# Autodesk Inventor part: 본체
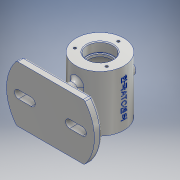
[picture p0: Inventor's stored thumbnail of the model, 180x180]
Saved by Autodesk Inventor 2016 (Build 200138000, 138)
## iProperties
Created: 2017-12
Part Number: 본체
Material: 알루미늄 6061
Document SubType Name: Modeling
Designer: 605-03
Density: 2.7 g/cm^3
Appearance: 알루미늄 - 평지
Mass: 464.488 g
Surface Area: 487.59 cm^2
Volume: 172.033 cm^3
Author: 605-03
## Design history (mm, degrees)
sketch "스케치1"
  geometry: L1 (0, 0)-(30, 0); L2 (30, 0)-(30, -70); L3 (30, -70)-(0, -70); L4 (0, 0)-(0, -70); L5 (16, 0)-(16, -11.7); L6 (15.7, -12)-(14, -12); L7 (14, -12)-(14, -15); L8 (14, -15)-(22, -15); L9 (25, -18)-(25, -52); L10 (22, -55)-(14, -55); L11 (14, -55)-(14, -58); L12 (14, -58)-(15.7, -58); L13 (16, -58.3)-(16, -70); A1 r 0.3 centre (15.7, -58.3) between (16, -58.3) and (15.7, -58); A2 r 0.3 centre (15.7, -11.7) between (15.7, -12) and (16, -11.7); A3 r 3 centre (22, -18) between (25, -18) and (22, -15); A4 r 3 centre (22, -52) between (22, -55) and (25, -52); 4 further points
  constraints: 26 end point, 10 perpendicular, 10 point on line, 8 point on circle, 8 tangent, 4 centre point, 2 vertical, 1 equal radius, 1 horizontal
  dimensions: "d0" = 60 diameter of L2 L4; "d1" = 70 distance of L1.start L3.end; "d2" = 12 distance of L5.start point (16, -12); "d3" = 12 distance of point (16, -58) L13.end; "d4" = 40 distance of point (25, -15) point (25, -55); "d5" = 3 distance of L10.end L11.end; "d6" = 32 diameter of L5 L4; "d7" = 28 diameter of L7 L4; "d8" = 50 diameter of L9 L4; "d9" = 32 diameter of L13 L4; "d10" = 28 diameter of L11 L4; "d11" = 0.3 radius of A1; "d12" = 3 radius of A3; "d13" = 3 radius of A4
revolve "회전1" sketch "스케치1" stored, may be unused: angle "d14" = 90 deg
sketch "스케치2" dims "d15" = 46
  geometry: C1 r 30 at (0, 0) reference; C2 r 16 at (0, 0) reference; 5 further points
  constraints: 2 vertical alignment, 1 coincident, 6 other
  dimensions: "d18" = 360 deg dimension on point (0, 0) point (0, 23) (derived)
hole "구멍1" sketch "스케치2" at (0, 23), (-19.919, -11.5), (19.919, -11.5) diameter "d20" = 3.242; stored, may be unused: countersink angle "d24" = 90 deg, drill point angle "d26" = 118 deg; dims "d21" = 8, "d22" = 4, "d23" = 2, "d25" = 10
sketch "스케치3" dims "d27" = 46
  geometry: C1 r 30 at (0, 0) reference; C2 r 16 at (0, 0) reference; 5 further points
  constraints: 2 vertical alignment, 1 coincident, 6 other
  dimensions: "d30" = 360 deg dimension on point (0, 0) point (0, 23) (derived)
hole "구멍2" sketch "스케치3" at (0, 23), (-19.919, -11.5), (19.919, -11.5) diameter "d32" = 3.242; stored, may be unused: countersink angle "d36" = 90 deg, drill point angle "d38" = 118 deg; dims "d33" = 8, "d34" = 4, "d35" = 2, "d37" = 10
node "작업 평면2"
sketch "스케치6"
  geometry: L1 (42.426, -70)-(-42.426, -70); L2 (42.426, 0)-(-42.426, 0); L3 (-30, 0)-(30, 0) reference; L4 (-30, -70)-(30, -70) reference; L5 (0, 0)-(0, -70); L6 (-16, -70)-(16, -70) reference; A1 r 55 centre (0, -35) between (-42.426, 0) and (-42.426, -70); A2 r 55 centre (0, -35) between (42.426, -70) and (42.426, 0); 2 further points
  constraints: 6 end point, 4 point on circle, 3 midpoint, 2 centre point, 2 horizontal, 1 coincident, 1 vertical alignment
  dimensions: "d58" = 70 distance between parallel lines of L1 L2; "d59" = 35 distance from line of L2 A1.centre; "d60" = 110 diameter of A1; "d61" = 55 radius of A2
extrude "돌출2" join sketch "스케치6" distance "d62" = 10; taper "d63" = 0 deg
sketch "스케치7"
  geometry: L1 (42.426, 0)-(-42.426, 0) reference; L2 (-42.426, 70)-(42.426, 70) reference; L3 (42.426, 0)-(-42.426, 0) reference; L4 (-42.426, 0)-(-42.426, 70); L5 (-42.426, 70)-(42.426, 70) reference; L6 (42.426, 70)-(42.426, 0); L7 (0, 20)-(0, 50); L8 (5, 20)-(5, 50); L9 (-5, 50)-(-5, 20); L10 (-42.426, 35)-(42.426, 35); L11 (-40, 35)-(-24, 35); L12 (-40, 30)-(-24, 30); L13 (-24, 40)-(-40, 40); L14 (24, 35)-(40, 35); L15 (24, 30)-(40, 30); L16 (40, 40)-(24, 40); A1 r 55 centre (0, 35) between (42.426, 0) and (42.426, 70) reference; A2 r 55 centre (0, 35) between (-42.426, 70) and (-42.426, 0) reference; A3 r 5 centre (0, 20) between (-5, 20) and (5, 20); A4 r 5 centre (0, 50) between (5, 50) and (-5, 50); A5 r 5 centre (-40, 35) between (-40, 40) and (-40, 30); A6 r 5 centre (-24, 35) between (-24, 30) and (-24, 40); A7 r 5 centre (24, 35) between (24, 40) and (24, 30); A8 r 5 centre (40, 35) between (40, 30) and (40, 40); 5 further points
  constraints: 30 end point, 12 point on circle, 12 tangent, 6 centre point, 6 midpoint, 3 parallel, 2 horizontal, 2 horizontal alignment, 2 perpendicular, 1 coincident, 1 vertical
  dimensions: "d64" = 10 diameter of A4; "d65" = 30 distance of L7.start L7.end; "d66" = 10 diameter of A6; "d67" = 16 distance of L11.end L11.start; "d68" = 24 distance of A1.centre L11.end; "d69" = 10 diameter of A8; "d70" = 16 distance of L14.end L14.start; "d71" = 24 distance of A1.centre L14.start
  node "절단 모서리 투영4"
extrude "돌출3" join sketch "스케치7" stored distance "d72" = 10; taper "d73" = 0 deg
extrude "돌출4" cut sketch "스케치7" stored distance "d74" = 10; taper "d75" = 0 deg
node "작업 평면3"
sketch "스케치8"
  geometry: C1 r 8 at (0, -35); 1 further point
  constraints: 1 centre point, 1 vertical alignment
  dimensions: "d77" = 16 diameter of C1; "d78" = 35 distance of point (0, 0) C1.centre
extrude "돌출5" join sketch "스케치8" stored distance "d79" = 10; taper "d80" = 0 deg
hole "구멍3" diameter "d83" = 8; stored, may be unused: countersink angle "d87" = 90 deg, drill point angle "d89" = 0 deg; dims "d81" = 10, "d82" = 10, "d84" = 8, "d85" = 4, "d86" = 2, "d88" = 26
chamfer "모따기1" distance "d90" = 1; stored, may be unused: second distance "d91" = 2, angle "d92" = 45 deg
chamfer "모따기2" distance "d93" = 1; stored, may be unused: second distance "d94" = 2, angle "d95" = 45 deg
chamfer "모따기3" distance "d96" = 1; stored, may be unused: second distance "d97" = 2, angle "d98" = 45 deg
fillet "모깎기1" dims "d99" = 3
node "작업 평면4"
node "작업 평면5"
sketch "스케치10"
  geometry: 2 further points
  constraints: 1 vertical alignment, 1 other
  dimensions: "d103" = 35 distance of point (0, 35) point (0, 0)
feature "엠보싱2" sketch "스케치10" dims "d0" = 60, "d1" = 70, "d2" = 12, "d3" = 12, "d4" = 40, "d5" = 3, "d6" = 32, "d7" = 28, "d8" = 50, "d9" = 32, "d10" = 28, "d11" = 0.3, "d12" = 3, "d13" = 3, "d104" = 0.5, "d105" = 0
fillet "모깎기2" dims "d106" = 5
node "솔리드1"
node "투영된 루프2"
node "절단 모서리 투영1"
node "절단 모서리 투영2"
other parameters: "d56" = -62, "d76" = 37
